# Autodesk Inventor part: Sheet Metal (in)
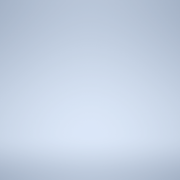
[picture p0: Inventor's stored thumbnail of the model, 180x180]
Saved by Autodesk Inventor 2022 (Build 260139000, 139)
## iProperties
Created: 2021-02
Part Number: Sheet Metal (in)
Material: Generico
Document SubType Name: Sheet Metal
Density: 1 g/cm^3
Sheet Metal Rule: Default
Appearance: Default
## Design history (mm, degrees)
other parameters: "Spessore" = 3.048, "RaggioPiega" = 3.048 (= Spessore), "LarghezzaScaricoPiega" = 3.048 (= Spessore), "ProfonditàScaricoPiega" = 1.524 (= 0.5 x Spessore), "DimensioniScaricoAngolo" = 12.192 (= 4 x Spessore), "SeamGap" = 0.00508, "ResiduoMinimo" = 6.096 (= 2 x Spessore), "RaggioTransizione" = 3.048 (= RaggioPiega), "Dimensione_raggio_Jacobi" = 3.048 (= RaggioPiega), "DimensioneGioco" = 3.048 (= Spessore)
